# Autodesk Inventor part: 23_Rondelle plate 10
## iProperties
Created: 2000-12
Part Number: 23_Rondelle plate 10
Material: Par défaut
Document SubType Name: Modélisation
Designer: Administrateur
Control State: 0
Master: False
Checked Out: False
Shininess: 20.0
Length Units: 11269
Angle Units: 11279
Time Units: 11290
Mass Units: 11283
Length Display Precision: 3
Angle Display Precision: 2
Density: 0.0
Volumn: 0.0
Area: 0.0
PropertySet Name: Model Information
Author: Administrateur
